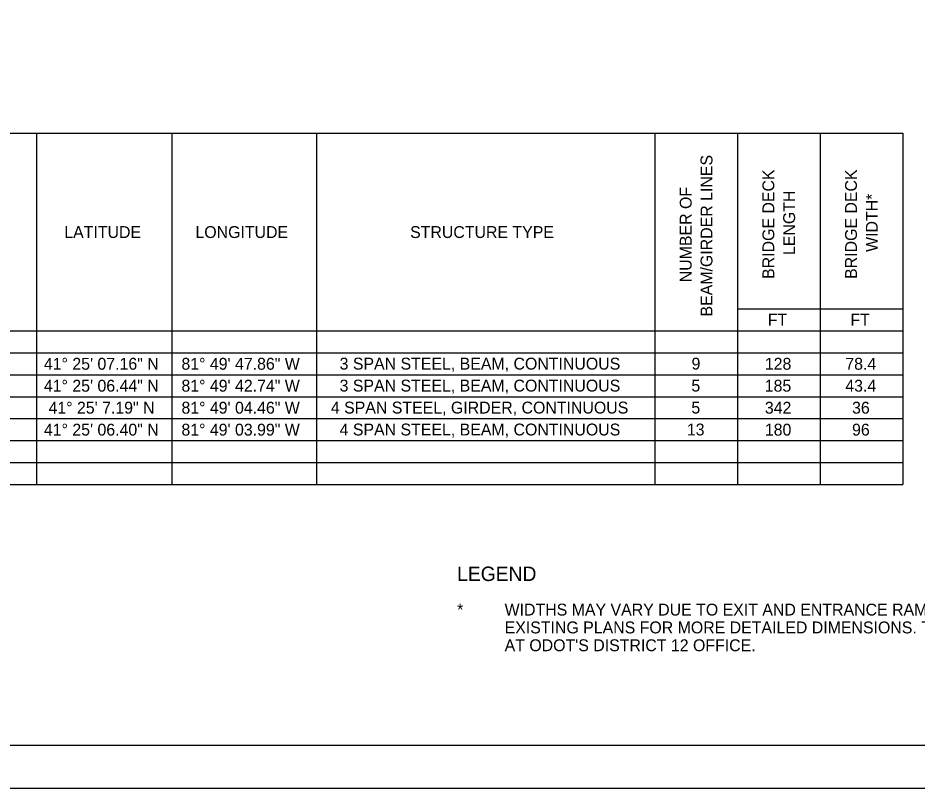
# Model space of a CAD drawing. Extents: x 0 to 1336, y 0 to 440.
# Drawn here: x 342.4 to 554.3, y 0 to 181.5 of the extents above; entities that cross this region are included whole.
import ezdxf

# ---------------------------------------------------------------- set-up
doc = ezdxf.new("R2010")
doc.units = 0
for name, color, linetype in [('DR_P_Text', 7, 'Continuous'), ('SH_Border', 7, 'Continuous'), ('SH_Cut_Line', 7, 'Continuous'), ('SN_P_Text', 7, 'Continuous')]:
    doc.layers.add(name, color=color, linetype=linetype)

msp = doc.modelspace()

# ---------------------------------------------------------------- linework, layer by layer
at = {"layer": 'SH_Border'}
msp.add_lwpolyline([(30, 430), (670, 430), (670, 10), (30, 10)], close=True, dxfattribs=at)
at = {"layer": 'SH_Cut_Line'}
msp.add_lwpolyline([(0, 0), (680, 0), (680, 440), (0, 440)], close=True, dxfattribs=at)
at = {"layer": 'SN_P_Text'}
for p, q in [((124.85, 154.3), (550.93, 154.3)), ((346.72, 154.3), (346.72, 71.51)), ((378.67, 154.3), (378.67, 71.51)), ((412.76, 154.3), (412.76, 71.51)), ((492.5, 154.3), (492.5, 71.51)), ((511.98, 154.3), (511.98, 71.51)), ((531.46, 154.3), (531.46, 71.51)), ((550.93, 154.3), (550.93, 71.51)), ((511.98, 112.9), (550.93, 112.9)), ((124.85, 107.73), (550.93, 107.73)), ((124.85, 102.56), (550.93, 102.56)), ((124.85, 97.38), (550.93, 97.38)), ((124.85, 92.21), (550.93, 92.21)), ((124.85, 87.04), (550.93, 87.04)), ((124.85, 81.86), (550.93, 81.86)), ((124.85, 76.69), (550.93, 76.69)), ((124.85, 71.51), (550.93, 71.51))]:
    msp.add_line(p, q, dxfattribs=at)

# ---------------------------------------------------------------- texts
at = {"layer": 'DR_P_Text'}
for s, height, p in [('LEGEND', 3.4, (445.9, 48.78)), ('*', 2.8, (445.9, 40.64)), ('WIDTHS MAY VARY DUE TO EXIT AND ENTRANCE RAMPS ON THE STRUCTURE. SEE', 2.8, (457.1, 40.64)), ('EXISTING PLANS FOR MORE DETAILED DIMENSIONS. THESE PLANS CAN BE VIEWED', 2.8, (457.1, 36.44)), ("AT ODOT'S DISTRICT 12 OFFICE.", 2.8, (457.1, 32.24))]:
    msp.add_text(s, height=height, dxfattribs=at).set_placement(p)
at = {"layer": 'SN_P_Text'}
for s, p in [('BEAM/GIRDER LINES', (506.09, 111.11)), ('BRIDGE DECK ', (520.67, 119.97)), ('BRIDGE DECK ', (540.15, 119.97)), ('NUMBER OF ', (501.19, 119.18)), ('LENGTH', (525.57, 125.6)), ('WIDTH*', (545.05, 126.33))]:
    msp.add_text(s, height=2.8, rotation=90, dxfattribs=at).set_placement(p)
for s, p in [('LATITUDE', (353.3, 129.61)), ('LONGITUDE', (384.22, 129.61)), ('STRUCTURE TYPE', (434.82, 129.61)), ('FT', (519.13, 108.95)), ('FT', (538.61, 108.95)), ('41° 25\' 07.16" N', (348.5, 98.57)), ('81° 49\' 47.86" W', (380.92, 98.57)), ('3 SPAN STEEL, BEAM, CONTINUOUS', (418.2, 98.6)), ('9', (501.16, 98.6)), ('128', (518.44, 98.57)), ('78.4', (537.41, 98.57)), ('41° 25\' 06.44" N', (348.5, 93.4)), ('81° 49\' 42.74" W', (380.92, 93.4)), ('3 SPAN STEEL, BEAM, CONTINUOUS', (418.2, 93.43)), ('5', (501.12, 93.43)), ('185', (518.42, 93.4)), ('43.4', (537.41, 93.4)), ('41° 25\' 7.19" N', (349.59, 88.22)), ('81° 49\' 04.46" W', (380.92, 88.22)), ('4 SPAN STEEL, GIRDER, CONTINUOUS', (416.14, 88.25)), ('5', (501.12, 88.25)), ('342', (518.44, 88.22)), ('36', (539, 88.22)), ('41° 25\' 06.40" N', (348.5, 83.05)), ('81° 49\' 03.99" W', (380.92, 83.05)), ('4 SPAN STEEL, BEAM, CONTINUOUS', (418.2, 83.08)), ('13', (500.06, 83.08)), ('180', (518.44, 83.05)), ('96', (539, 83.05))]:
    msp.add_text(s, height=2.8, dxfattribs=at).set_placement(p)

doc.saveas('drawing.dxf')
